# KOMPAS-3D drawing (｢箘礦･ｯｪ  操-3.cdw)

Referenced files: Автосцепка СА-3.cdw
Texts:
  ВСТАВЬ СВОЙ ШИФР
  Автосцепка СА-3
  GooDMaN
  Домашний пк
  Текст на чертеже
  Размерные надписи
  Шероховатость
  Линия-выноска #1
  Линия-выноска #2
  Линия-выноска #3
  Отклонения формы и база
  Заголовок таблицы
  Ячейка таблицы
  Стрелка вида
  Обозначение изменения
  Фигурная скобка
  Номер узла
  Марка координационной оси
  VRCB
  Выносная надпись
  Обозначение узла
  Марка/позиционное обозначение с линией-выноской
  Марка/позиционное обозначение на линии
  Марка/позиционное обозначение без линии-выноски
  Слой 1
  Иванов
  ПУ-1 гр. № 1
  ПЭР.30.4.00.00.02.ВО-
Dimensions and other numbers on the sheet: 7; 1; 2; 3; 4; 5; 6; 0; 8; 9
